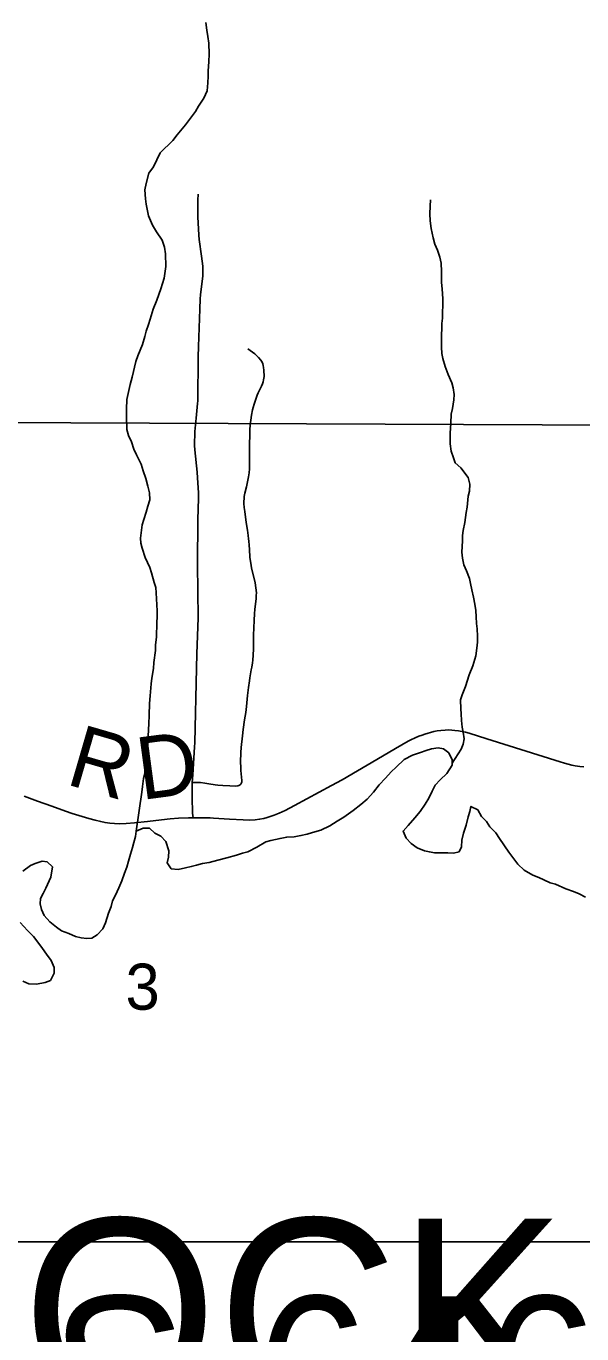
# Model space of a CAD drawing. Extents: x 0 to 34, y 0 to 22.
# Drawn here: x 23.665 to 24.17, y 16.809 to 17.999 of the extents above; entities that cross this region are included whole.
import ezdxf

# ---------------------------------------------------------------- set-up
doc = ezdxf.new("R2010")
doc.units = 0
for name, color, linetype in [('GM_X_Corporation', 7, 'Continuous'), ('GM_X_County_Road', 7, 'Continuous'), ('GM_X_County_Road_Text', 7, 'Continuous'), ('GM_X_Minor_River', 7, 'Continuous'), ('GM_X_Section_Text', 7, 'Continuous'), ('GM_X_Township_Road', 7, 'Continuous'), ('GM_X_Township_Text', 7, 'Continuous'), ('SH_Text', 7, 'Continuous')]:
    doc.layers.add(name, color=color, linetype=linetype)

msp = doc.modelspace()

# ---------------------------------------------------------------- linework, layer by layer
at = {"layer": 'GM_X_Corporation'}
for points in [[(23.3004, 18.648), (24.3084, 18.6368), (24.3059, 18.5094), (24.2773, 17.6357), (23.2763, 17.6399)], [(23.2763, 17.6399), (24.2773, 17.6357), (24.2765, 17.4936), (24.2698, 16.6327), (23.7676, 16.6453), (23.2579, 16.628)]]:
    msp.add_lwpolyline(points, close=True, dxfattribs=at)
at = {"layer": 'GM_X_County_Road'}
msp.add_lwpolyline([(23.6629, 17.2985), (23.6749, 17.294), (23.6878, 17.2893), (23.7003, 17.2848), (23.7065, 17.2827), (23.7215, 17.2783), (23.7275, 17.2767), (23.7325, 17.2754), (23.7364, 17.2745), (23.7407, 17.2739), (23.745, 17.2735), (23.7498, 17.2733), (23.7555, 17.2735), (23.7631, 17.2742), (23.775, 17.2755), (23.7878, 17.277), (23.7956, 17.2778), (23.8033, 17.2785), (23.8122, 17.2789), (23.8165, 17.2789), (23.832, 17.2787), (23.8352, 17.2785), (23.8497, 17.2776), (23.862, 17.277), (23.8678, 17.2768), (23.8729, 17.2771), (23.8771, 17.2775), (23.8808, 17.2783), (23.884, 17.2792), (23.8867, 17.28), (23.8904, 17.2813), (23.8949, 17.2831), (23.9004, 17.2856), (23.9089, 17.29), (23.9426, 17.3082), (23.9523, 17.3135), (23.989, 17.3348), (24.0009, 17.3418), (24.0124, 17.3485), (24.0148, 17.3497), (24.0186, 17.3515), (24.0221, 17.353), (24.0252, 17.3541), (24.0276, 17.355), (24.0357, 17.3572), (24.0387, 17.3578), (24.0421, 17.3583), (24.0461, 17.3587), (24.0491, 17.3588), (24.0521, 17.3587), (24.0549, 17.3584), (24.058, 17.3579), (24.0646, 17.3566), (24.0679, 17.3557), (24.084, 17.3507), (24.1507, 17.3296), (24.1545, 17.3285), (24.1614, 17.3268), (24.1643, 17.3262), (24.1686, 17.3256), (24.1723, 17.3251)], dxfattribs=at)
at = {"layer": 'GM_X_Minor_River'}
for points in [[(23.7647, 17.2666), (23.7699, 17.302), (23.7706, 17.3073), (23.7714, 17.3145), (23.7725, 17.3191), (23.7732, 17.327), (23.7747, 17.3388), (23.7754, 17.3464), (23.7758, 17.3593), (23.7761, 17.3643), (23.7765, 17.3722), (23.7768, 17.3829), (23.7776, 17.3897), (23.7783, 17.4007), (23.779, 17.406), (23.7805, 17.4148), (23.7809, 17.4201), (23.7824, 17.4311), (23.7823, 17.436), (23.7831, 17.4436), (23.7834, 17.4562), (23.7838, 17.4619), (23.7838, 17.4672), (23.7833, 17.4782), (23.7829, 17.4835), (23.7825, 17.4885), (23.781, 17.493), (23.7787, 17.5017), (23.7772, 17.5067), (23.773, 17.5158), (23.7703, 17.5241), (23.7691, 17.5287), (23.7687, 17.5332), (23.7702, 17.5454), (23.7717, 17.5503), (23.7739, 17.5568), (23.7754, 17.5625), (23.7773, 17.5682), (23.7769, 17.5746), (23.7754, 17.5807), (23.7735, 17.5876), (23.7712, 17.5944), (23.7692, 17.6005), (23.765, 17.6092), (23.7627, 17.6141), (23.7604, 17.6209), (23.7578, 17.6266), (23.7562, 17.632), (23.7558, 17.6433), (23.7558, 17.6506), (23.7561, 17.6593), (23.7591, 17.673), (23.761, 17.6798), (23.7644, 17.6939), (23.7662, 17.6992), (23.7704, 17.7094), (23.7726, 17.7167), (23.7737, 17.7216), (23.776, 17.7277), (23.7775, 17.7326), (23.7801, 17.7417), (23.7835, 17.7497), (23.7873, 17.76), (23.7903, 17.7699), (23.7918, 17.7805), (23.7913, 17.7919), (23.7906, 17.798), (23.7883, 17.8044), (23.7833, 17.812), (23.7795, 17.8181), (23.776, 17.8264), (23.7737, 17.837), (23.7733, 17.842), (23.7725, 17.8503), (23.7737, 17.856), (23.7763, 17.8655), (23.7804, 17.8712), (23.7865, 17.8838), (23.7982, 17.8952), (23.802, 17.9001), (23.8095, 17.9093), (23.8186, 17.9214), (23.8216, 17.9264), (23.8262, 17.9336), (23.8292, 17.9404), (23.8299, 17.9477), (23.8303, 17.9537), (23.8302, 17.9583), (23.831, 17.967), (23.8313, 17.9735), (23.8309, 17.9837), (23.8298, 17.9898), (23.829, 17.9955), (23.8282, 18.0023)], [(24.0523, 17.3285), (24.0606, 17.3413), (24.0625, 17.3458), (24.0632, 17.3508), (24.0624, 17.3568), (24.0616, 17.3614), (24.0609, 17.3675), (24.0605, 17.3735), (24.0601, 17.3781), (24.06, 17.3861), (24.0615, 17.3906), (24.0646, 17.3982), (24.0679, 17.4089), (24.0713, 17.4172), (24.074, 17.4263), (24.0747, 17.4332), (24.0754, 17.4385), (24.0754, 17.4442), (24.075, 17.4507), (24.0746, 17.4556), (24.0742, 17.4617), (24.0738, 17.4674), (24.073, 17.4731), (24.0719, 17.4795), (24.0703, 17.4863), (24.0692, 17.492), (24.068, 17.4966), (24.0653, 17.5034), (24.063, 17.5091), (24.0619, 17.5152), (24.0611, 17.5205), (24.0618, 17.5308), (24.0618, 17.5357), (24.0625, 17.5403), (24.064, 17.5475), (24.0651, 17.5566), (24.0659, 17.5615), (24.067, 17.5714), (24.0681, 17.576), (24.0685, 17.5824), (24.0669, 17.5885), (24.0601, 17.5972), (24.0551, 17.6018), (24.0536, 17.6063), (24.0513, 17.6124), (24.0505, 17.6192), (24.0505, 17.6287), (24.0512, 17.6378), (24.0515, 17.6462), (24.0527, 17.6511), (24.0538, 17.6591), (24.0541, 17.664), (24.0534, 17.6701), (24.0522, 17.6747), (24.0488, 17.6823), (24.0461, 17.6895), (24.0438, 17.6967), (24.043, 17.7012), (24.0426, 17.7069), (24.0426, 17.713), (24.0426, 17.7187), (24.0429, 17.7236), (24.0429, 17.7286), (24.0436, 17.7335), (24.0436, 17.7388), (24.044, 17.7449), (24.044, 17.751), (24.0432, 17.7601), (24.0428, 17.7658), (24.0427, 17.776), (24.0423, 17.7836), (24.0412, 17.7889), (24.0389, 17.7954), (24.0366, 17.8007), (24.035, 17.8064), (24.0331, 17.8151), (24.0323, 17.822), (24.0319, 17.8284), (24.0323, 17.8353), (24.0326, 17.841)], [(23.8828, 17.257), (23.8874, 17.2581), (23.8957, 17.2601), (23.9018, 17.2612), (23.9086, 17.2616), (23.9147, 17.2627), (23.9204, 17.2639), (23.9253, 17.2654), (23.9329, 17.2677), (23.9409, 17.2715), (23.9477, 17.2757), (23.9537, 17.2795), (23.9621, 17.2856), (23.9693, 17.291), (23.9749, 17.2959), (23.9806, 17.302), (23.9859, 17.3088), (23.9916, 17.3149), (23.9969, 17.3206), (24.0014, 17.3248), (24.0086, 17.332), (24.0162, 17.3359), (24.0234, 17.3381), (24.0287, 17.3401), (24.0336, 17.3416), (24.0397, 17.3424), (24.0446, 17.3416), (24.0492, 17.3378), (24.0523, 17.3317), (24.0523, 17.3268), (24.0474, 17.3192), (24.0413, 17.3135), (24.0368, 17.3085), (24.0341, 17.3032), (24.0311, 17.2968), (24.0277, 17.2911), (24.0232, 17.2846), (24.0183, 17.2789), (24.0122, 17.2717), (24.0077, 17.2667), (24.0104, 17.2603), (24.0149, 17.2553), (24.0206, 17.2516), (24.0271, 17.2489), (24.0317, 17.2478), (24.0362, 17.247), (24.0484, 17.247), (24.0537, 17.2467), (24.0586, 17.2478), (24.0609, 17.2524), (24.0612, 17.2585), (24.0627, 17.2649), (24.065, 17.2721), (24.0669, 17.2797), (24.0684, 17.2847), (24.0695, 17.2892), (24.0756, 17.2862), (24.079, 17.2801), (24.0836, 17.2756), (24.0866, 17.2707), (24.092, 17.265), (24.0954, 17.26), (24.1038, 17.2475), (24.1084, 17.2415), (24.1122, 17.2365), (24.1179, 17.2312), (24.1259, 17.2267), (24.1312, 17.2244), (24.1358, 17.2225), (24.1415, 17.2195), (24.1464, 17.2184), (24.1559, 17.2142), (24.1628, 17.2119), (24.1681, 17.2097), (24.1738, 17.2066)], [(23.6616, 17.2304), (23.6684, 17.2353), (23.6729, 17.2372), (23.679, 17.2395), (23.6836, 17.2388), (23.6885, 17.2342), (23.687, 17.2247), (23.6825, 17.2148), (23.6799, 17.2099), (23.6776, 17.2053), (23.6772, 17.2004), (23.6784, 17.1955), (23.6811, 17.1898), (23.686, 17.1841), (23.6921, 17.1792), (23.6967, 17.1761), (23.7035, 17.1735), (23.7096, 17.1708), (23.7145, 17.1697), (23.7199, 17.169), (23.7244, 17.1693), (23.7293, 17.1724), (23.7343, 17.1777), (23.7369, 17.1834), (23.7395, 17.1922), (23.7418, 17.1982), (23.7433, 17.2032), (23.7459, 17.2085), (23.7489, 17.215), (23.7516, 17.2214), (23.7542, 17.2283), (23.7561, 17.234), (23.7576, 17.2393), (23.7595, 17.2457), (23.7613, 17.2518), (23.7625, 17.2564), (23.764, 17.2617), (23.7647, 17.2666), (23.7711, 17.2693), (23.7768, 17.2693), (23.7818, 17.2648), (23.7871, 17.2621), (23.7917, 17.2572), (23.7944, 17.2488), (23.794, 17.2431), (23.7929, 17.2378), (23.7967, 17.2325), (23.8028, 17.2318), (23.8096, 17.2333), (23.8149, 17.2345), (23.8195, 17.2356), (23.8252, 17.2371), (23.8312, 17.2383), (23.8392, 17.2402), (23.8472, 17.2425), (23.8559, 17.2448), (23.8616, 17.2467), (23.8665, 17.2478), (23.8745, 17.252), (23.8828, 17.257)], [(23.6615, 17.1301), (23.6669, 17.1278), (23.6741, 17.1275), (23.682, 17.129), (23.6866, 17.1309), (23.69, 17.1374), (23.69, 17.1427), (23.6873, 17.1491), (23.6831, 17.1548), (23.6793, 17.1598), (23.6751, 17.1658), (23.6713, 17.1708), (23.6659, 17.1764), (23.6591, 17.1836)]]:
    msp.add_lwpolyline(points, dxfattribs=at)
at = {"layer": 'GM_X_Township_Road'}
for points in [[(23.8165, 17.2789), (23.8161, 17.2831), (23.8159, 17.2877), (23.8156, 17.2929), (23.8156, 17.3046), (23.8157, 17.311), (23.8159, 17.3143), (23.8162, 17.318), (23.8179, 17.3433), (23.8181, 17.3469), (23.8195, 17.415), (23.8199, 17.4279), (23.8211, 17.4608), (23.8205, 17.5092), (23.8209, 17.5503), (23.8212, 17.5596), (23.8216, 17.5695), (23.8215, 17.5745), (23.8206, 17.5881), (23.8201, 17.5932), (23.818, 17.6135), (23.8178, 17.6175), (23.8181, 17.6304), (23.8192, 17.6425), (23.8206, 17.6557), (23.8207, 17.6581), (23.8212, 17.6981), (23.8216, 17.7075), (23.8226, 17.7415), (23.8229, 17.751), (23.8232, 17.7547), (23.8253, 17.7718), (23.8255, 17.7743), (23.8253, 17.7807), (23.8241, 17.7898), (23.8222, 17.8051), (23.8219, 17.809), (23.821, 17.8203), (23.8208, 17.8253), (23.8207, 17.831), (23.8208, 17.8409), (23.8211, 17.8463)], [(23.8157, 17.311), (23.8233, 17.3109), (23.8273, 17.3103), (23.8309, 17.3097), (23.8367, 17.3088), (23.8392, 17.3086), (23.8435, 17.3083), (23.85, 17.308), (23.8554, 17.3077), (23.8573, 17.3079), (23.8582, 17.3082), (23.8593, 17.3089), (23.8599, 17.3095), (23.8605, 17.3105), (23.8608, 17.3115), (23.8609, 17.3127), (23.8601, 17.322), (23.8599, 17.325), (23.8598, 17.3295), (23.86, 17.3382), (23.8603, 17.3429), (23.8614, 17.3534), (23.8622, 17.3592), (23.8634, 17.368), (23.8644, 17.3747), (23.8651, 17.3801), (23.8662, 17.3901), (23.8671, 17.3974), (23.8678, 17.4033), (23.8681, 17.4061), (23.8688, 17.4097), (23.8694, 17.4134), (23.8699, 17.4159), (23.8707, 17.4198), (23.8709, 17.4221), (23.8711, 17.4269), (23.8714, 17.4326), (23.8716, 17.4449), (23.8717, 17.4518), (23.872, 17.4584), (23.8724, 17.4648), (23.8727, 17.4683), (23.8734, 17.4736), (23.8738, 17.478), (23.874, 17.4812), (23.8741, 17.4834), (23.8737, 17.4882), (23.8731, 17.4926), (23.8698, 17.5064), (23.869, 17.5104), (23.8685, 17.5139), (23.8682, 17.516), (23.8679, 17.5228), (23.8676, 17.5269), (23.8673, 17.5305), (23.8671, 17.5325), (23.8666, 17.5357), (23.866, 17.5404), (23.8649, 17.5475), (23.8635, 17.5575), (23.863, 17.5611), (23.8627, 17.5648), (23.8631, 17.5711), (23.8637, 17.5743), (23.865, 17.5801), (23.8664, 17.5859), (23.867, 17.5892), (23.8676, 17.5928), (23.8679, 17.5963), (23.868, 17.5986), (23.8679, 17.6095), (23.8678, 17.6175), (23.8681, 17.6282), (23.8683, 17.6317), (23.8686, 17.6363), (23.8691, 17.6406), (23.8698, 17.6453), (23.8705, 17.65), (23.8711, 17.6522), (23.872, 17.6553), (23.8737, 17.6596), (23.8749, 17.6634), (23.8757, 17.6654), (23.8789, 17.6717), (23.8798, 17.6738), (23.8804, 17.6756), (23.8807, 17.6773), (23.8811, 17.6804), (23.8809, 17.6862), (23.8807, 17.6884), (23.8802, 17.6903), (23.8799, 17.6919), (23.8793, 17.6933), (23.8781, 17.6952), (23.8762, 17.6975), (23.8743, 17.6996), (23.8726, 17.7009), (23.8664, 17.7056)]]:
    msp.add_lwpolyline(points, dxfattribs=at)
at = {"layer": 'SH_Text'}
msp.add_lwpolyline([(23.3742, 16.893), (23.3742, 16.653), (24.7353, 16.653), (24.7353, 16.893)], close=True, dxfattribs=at)

# ---------------------------------------------------------------- texts
at = {"layer": 'GM_X_County_Road_Text'}
for s, rotation, p in [('R', 343.7624, (23.6993, 17.3098)), ('D', 7.5793, (23.7692, 17.2949))]:
    msp.add_text(s, height=0.0568, rotation=rotation, dxfattribs=at).set_placement(p)
at = {"layer": 'GM_X_Section_Text'}
msp.add_text('3', height=0.0419, rotation=0, dxfattribs=at).set_placement((23.755, 17.1042))
at = {"layer": 'GM_X_Township_Text'}
msp.add_text('STOCK', height=0.17045, rotation=0, dxfattribs=at).set_placement((23.37, 16.7437))
at = {"layer": 'SH_Text'}
msp.add_text('HAS-646-1.15', height=0.14, dxfattribs=at).set_placement((23.426, 16.7035))

doc.saveas('drawing.dxf')
